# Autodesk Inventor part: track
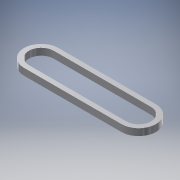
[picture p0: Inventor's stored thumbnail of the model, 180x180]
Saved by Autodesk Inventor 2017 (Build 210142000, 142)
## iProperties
Created: 2017-04
Part Number: track
Material: ABS Plastic
Document SubType Name: Modeling
Designer: 1717440
Density: 1.06 g/cm^3
Appearance: Smooth - White
Author: 1717440
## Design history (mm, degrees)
sketch "Sketch1"
  geometry: L1 (-53.138, 79.988)-(-53.138, 86.338); L2 (-53.138, 86.338)-(-81.713, 86.338); L3 (-53.138, 79.988)-(-81.713, 79.988); L4 (-53.138, 79.888)-(-81.713, 79.888); L5 (-81.713, 86.438)-(-53.138, 86.438); L6 (-53.138, 78.48)-(-81.713, 78.48); L7 (-81.713, 87.847)-(-53.138, 87.847); A1 r 3.175 centre (-53.138, 83.163) between (-53.138, 79.988) and (-53.138, 86.338) reference; A2 r 3.175 centre (-81.713, 83.163) between (-81.713, 86.338) and (-81.713, 79.988); A3 r 3.175 centre (-53.138, 83.163) between (-53.138, 79.988) and (-53.138, 86.338); A4 r 3.275 centre (-81.713, 83.163) between (-81.713, 86.438) and (-81.713, 79.888); A5 r 4.683 centre (-81.713, 83.163) between (-81.713, 87.847) and (-81.713, 78.48); A6 r 3.275 centre (-53.138, 83.163) between (-53.138, 79.888) and (-53.138, 86.438); A7 r 4.683 centre (-53.138, 83.163) between (-53.138, 78.48) and (-53.138, 87.847); 1 further point
  constraints: 14 end point, 14 point on circle, 6 centre point, 1 coincident, 1 concentric, 1 horizontal, 1 perpendicular, 1 tangent, 1 vertical, 4 other
  dimensions: "d0" = 28.575 distance of L1.end L2.end; "d1" = 28.575 distance of L1.start L3.end; "d2" = 0.1 radial gap between concentric circles of A2 A4; "d3" = 1.4084 radial gap between concentric circles of A4 A5
extrude "Extrusion1" new body sketch "Sketch1" distance "d4" = 2; taper "d5" = 0 deg
workplane "Work Plane1"
sketch "Sketch3"
  geometry: L1 (-53.307, 88.073)-(0, 97); L2 (-53.307, 83.39)-(0, 83.39); L3 (-53.307, 78.707)-(0, 69.78); L4 (0, 69.78)-(0, 97); L5 (-4.474, 91.715)-(-4.474, 75.065); L6 (-4.474, 75.065)-(-23.819, 78.305); L7 (-30.99, 79.505)-(-44.301, 81.734); L8 (-44.301, 85.046)-(-30.99, 87.275); L9 (-23.819, 88.475)-(-4.474, 91.715); L10 (0, 69.78)-(-4.474, 75.065); L11 (0, 97)-(-4.474, 91.715); C1 r 3.225 at (-26.654, 83.39); C2 r 1 at (-2.237, 72.423); C3 r 1 at (-2.237, 94.357); A1 r 4.683 centre (-53.307, 83.39) between (-53.307, 78.707) and (-53.307, 88.073) reference; A2 r 9.157 centre (-53.307, 83.39) between (-44.301, 81.734) and (-44.301, 85.046); A3 r 5.822 centre (-26.654, 83.39) between (-23.819, 78.305) and (-23.819, 88.475); A4 r 5.822 centre (-26.654, 83.39) between (-30.99, 87.275) and (-30.99, 79.505); 1 further point
  constraints: 22 end point, 6 centre point, 6 point on circle, 4 midpoint, 1 horizontal, 1 symmetric about line, 1 vertical
  dimensions: "d10" = 6.45 diameter of C1; "d16" = 2 diameter of C2; "d17" = 2 diameter of C3
workplane "Work Plane2"
extrude "Extrusion4" join sketch "Sketch3" distance "d18" = 2; taper "d19" = 0 deg
body "Solid1"
node "Reference1"
